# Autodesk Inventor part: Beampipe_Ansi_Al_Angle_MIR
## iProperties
Shininess: 64.0
Length Units: 11272
Angle Units: 11279
Time Units: 11290
Mass Units: 11286
Length Display Precision: 3
Angle Display Precision: 2
Compacted: True
Part Number: Beampipe_Ansi_Al_Angle_MIR
Document SubType Name: Modeling
Created: 2004-08
Designer: John Blackburn
Manufacturer: Standard
Standards Organization: Custom
Material: Aluminum-6061
Density: 0.0
Volumn: 0.0
Area: 0.0
PropertySet Name: Model Information
Control State: 0
Master: False
Checked Out: False
Author: John Blackburn
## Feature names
1. Extrusion1
2. Extrusion2
3. Extrusion6
